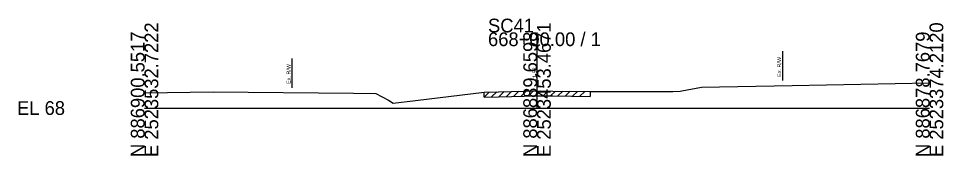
# Model space of a CAD drawing. Extents: x -26 to 183, y -10 to 24021.
# Drawn here: x -25.7 to 162.8, y 1490.3 to 1518.3 of the extents above; entities that cross this region are included whole.
import ezdxf

# ---------------------------------------------------------------- set-up
doc = ezdxf.new("R2010")
doc.units = 0
for name, color, linetype in [('RD_GPK_XS_Cell', 7, 'Continuous'), ('RD_XS_ExGround', 7, 'Continuous'), ('RD_XS_ExPaveRet', 7, 'Continuous'), ('RD_XS_ExRW', 7, 'Continuous'), ('RD_XS_TX_Elev_EX', 7, 'Continuous')]:
    doc.layers.add(name, color=color, linetype=linetype)

msp = doc.modelspace()

# ---------------------------------------------------------------- linework, layer by layer
at = {"layer": 'RD_GPK_XS_Cell'}
for p, q in [((80, 1500), (80, 1515.44)), ((0, 1500), (80, 1500)), ((80, 1500), (160, 1500))]:
    msp.add_line(p, q, dxfattribs=at)
at = {"layer": 'RD_XS_ExGround'}
for p, q in [((113.53, 1504.28), (131.99, 1504.63)), ((131.99, 1504.63), (160, 1505.15)), ((0, 1503.1), (13.95, 1503.32)), ((13.95, 1503.32), (42.57, 1503.01)), ((42.57, 1503.01), (47.12, 1502.95)), ((47.12, 1502.95), (49.72, 1501.6)), ((55.22, 1501.56), (69.24, 1503.23)), ((69.24, 1503.23), (72.17, 1503.32)), ((72.17, 1503.32), (80.02, 1503.52)), ((80.02, 1503.52), (83.24, 1503.47)), ((83.24, 1503.47), (90.85, 1503.35)), ((90.85, 1503.35), (107.7, 1503.38)), ((107.7, 1503.38), (109.15, 1503.41)), ((109.15, 1503.41), (109.53, 1503.48)), ((109.53, 1503.48), (113.53, 1504.28)), ((49.72, 1501.6), (50.69, 1501.01)), ((50.69, 1501.01), (55.22, 1501.56))]:
    msp.add_line(p, q, dxfattribs=at)
at = {"layer": 'RD_XS_ExPaveRet'}
for p, q in [((69.24, 1502.23), (70.27, 1503.26)), ((69.24, 1502.23), (69.24, 1503.23)), ((70.74, 1502.28), (71.77, 1503.31)), ((72.24, 1502.32), (73.27, 1503.35)), ((73.74, 1502.36), (74.77, 1503.38)), ((75.24, 1502.4), (76.27, 1503.42)), ((76.74, 1502.44), (77.77, 1503.46)), ((78.24, 1502.48), (79.27, 1503.5)), ((79.74, 1502.51), (80.74, 1503.51)), ((81.24, 1502.5), (82.23, 1503.49)), ((82.74, 1502.48), (83.73, 1503.46)), ((84.24, 1502.46), (85.23, 1503.44)), ((85.74, 1502.43), (86.73, 1503.42)), ((87.24, 1502.41), (88.23, 1503.39)), ((88.74, 1502.39), (89.73, 1503.37)), ((90.85, 1503.35), (90.85, 1502.35)), ((69.24, 1502.23), (72.17, 1502.32)), ((72.17, 1502.32), (80.02, 1502.52)), ((80.02, 1502.52), (83.24, 1502.47)), ((83.24, 1502.47), (90.85, 1502.35))]:
    msp.add_line(p, q, dxfattribs=at)
at = {"layer": 'RD_XS_ExRW'}
for p, q in [((130, 1511.59), (130, 1505.59)), ((30, 1510.14), (30, 1504.14))]:
    msp.add_line(p, q, dxfattribs=at)

# ---------------------------------------------------------------- texts
at = {"layer": 'RD_GPK_XS_Cell'}
for s, p in [('SC41', (70, 1515.44)), ('668+00.00 / 1', (70, 1512.64)), ('EL 68', (-26, 1498.6))]:
    msp.add_text(s, height=2.8, dxfattribs=at).set_placement(p)
for s, p in [('E 2523532.7222', (2.8, 1490)), ('E 2523453.4671', (82.8, 1490)), ('E 2523374.2120', (162.8, 1490)), ('N 886900.5517', (0, 1490)), ('N 886889.6598', (80, 1490)), ('N 886878.7679', (160, 1490))]:
    msp.add_text(s, height=2.8, rotation=90, dxfattribs=at).set_placement(p)
at = {"layer": 'RD_XS_ExRW'}
for p in [(129.75, 1506.38), (29.75, 1504.93)]:
    msp.add_text('Ex. R/W ', height=0.8, rotation=90, dxfattribs=at).set_placement(p)
at = {"layer": 'RD_XS_TX_Elev_EX'}
msp.add_text('71.52', height=0.8, rotation=90, dxfattribs=at).set_placement((79.9, 1505.52))

doc.saveas('drawing.dxf')
